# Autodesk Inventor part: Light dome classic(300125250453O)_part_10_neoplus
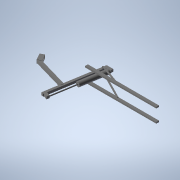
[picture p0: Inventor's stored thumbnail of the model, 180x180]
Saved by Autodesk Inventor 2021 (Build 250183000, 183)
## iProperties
Created: 2026-04
Part Number: Light dome classic(300125250453O)_part_10_neoplus
Material: Generic
Catalog Web Link: www.3dfindit.com
Description: Light dome classic_part_10_neoplus-
Vendor: KINGSPAN
Document SubType Name: Modeling
Designer: psAdmin
Manufacturer: KINGSPAN
Mass: 5382.09 g
Surface Area: 6581.21 cm^2
Volume: 5382.09 cm^3
Density: 1 g/cm^3
Appearance: PSOLRGB-255-255-255
Category: PARTsolutions
Company: KINGSPAN
Title: Light dome classic(300125250453O)_part_10_neoplus
Author: Cadenas PARTsolutions
PSOL_IDENT_0: {$CADENAS_DATA/23d-libs/kingspan_kla/light_dome_classic_neoplus/parts/part_10.prj},291 {VTYP=3D},{NB=
PSOL_IDENT_1: Light dome classic(300125250453O)_part_10_neoplus},{LINA=Light dome classic(300125250453O)_part_10_n
PSOL_IDENT_2: eoplus},{NN=Light dome classic_part_10_neoplus},{DATE=15.07.2024 10:56:16},{GEOMDATE=01.07.2024 07:0
PSOL_IDENT_3: 4:16},{VERSION=},{LINEID=10},{WBVAR=LODLEVEL,L,W,DP,OP,BA,OC},{WBNUMERIC=W}  {NB=Light dome classic(
PSOL_IDENT_4: 300125250453O)_part_10_neoplus},{LINA=Light dome classic(300125250453O)_part_10_neoplus},{KT=DUMMY},
PSOL_IDENT_5: {IDNR=},{PN=Light dome classic},{LODLEVEL=300},{L=125},{W=250},{DRIVE=1},{WX=125,250,300},{DP=4},{OP=
PSOL_IDENT_6: 5},{BA=3},{OC=O},{OPX='5','Pneumatic - NRWG F.6 LK'},{LX=1250},{XWX=2500},{HEI=1214.941},{VER=2},{DP
PSOL_IDENT_7: X='3', 'Fixed','1', 'Natural ventilation' ,'4','NSHE', '2', 'NSHEV'}
NB: Light dome classic(300125250453O)_part_10_neoplus
NN: Light dome classic_part_10_neoplus
NBSYN: $PN.($LODLEVEL.$L.$W.$DP.$OP.$BA.$OC.)_part_10_neoplus
LINA: Light dome classic(300125250453O)_part_10_neoplus
CATALOG: Light + Air
PN: Light dome classic
LODLEVEL: 300
L: 125
W: 250
DP: NSHE
OP: Pneumatic - NRWG F.6 LK
BA: PVC base 50 cm
OC: Open
SUPPLIER: KINGSPAN
ARTICLENO: Light dome classic(300125250453O)_part_10_neoplus
BOMINFO: Light dome classic(300125250453O)_part_10_neoplus
CREATOR: CADENAS GmbH
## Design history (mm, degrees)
sketch "Sketch_2"
  geometry: L1 (-549.928, -221.6)-(-536.377, -261.6); L2 (-536.377, -261.6)-(536.377, -261.6); L3 (536.377, -261.6)-(549.928, -221.6); L4 (549.928, -221.6)-(-549.928, -221.6)
  constraints: 8 end point
extrude "Extrusion1" join sketch "Sketch_2" distance "d0" = 20; taper "d1" = 0 deg
sketch "Sketch_1"
  geometry: L1 (567.69, 169.17)-(525.978, 292.296); L2 (525.978, 292.296)-(519.348, 290.05); L3 (519.348, 290.05)-(561.06, 166.924); L4 (561.06, 166.924)-(567.69, 169.17)
  constraints: 8 end point
extrude "Extrusion2" join sketch "Sketch_1" stored distance "d2" = 220; taper "d3" = 0 deg
sketch "Sketch_3"
  geometry: L1 (-519.348, 290.05)-(-525.978, 292.296); L2 (-525.978, 292.296)-(-567.69, 169.17); L3 (-567.69, 169.17)-(-561.06, 166.924); L4 (-561.06, 166.924)-(-519.348, 290.05)
  constraints: 8 end point
extrude "Extrusion3" join sketch "Sketch_3" stored distance "d4" = 220; taper "d5" = 0 deg
sketch "Sketch_4"
  geometry: L1 (-549.928, -221.6)-(-536.377, -261.6); L2 (-536.377, -261.6)-(536.377, -261.6); L3 (536.377, -261.6)-(549.928, -221.6); L4 (549.928, -221.6)-(-549.928, -221.6)
  constraints: 8 end point
extrude "Extrusion4" join sketch "Sketch_4" distance "d6" = 20; taper "d7" = 0 deg
sketch "Sketch_5"
  geometry: L1 (471.574, 66.971)-(73.269, 244.308); L2 (73.269, 244.308)-(65.134, 226.037); L3 (65.134, 226.037)-(463.44, 48.7); L4 (463.44, 48.7)-(471.574, 66.971)
  constraints: 8 end point
extrude "Extrusion5" join sketch "Sketch_5" stored distance "d8" = 172.9; taper "d9" = 0 deg
sketch "Sketch_8"
  geometry: L1 (5, 420)-(53.95, 27.63); L2 (53.95, 27.63)-(118.95, 27.63); L3 (118.95, 27.63)-(167.9, 420); L4 (167.9, 420)-(167.9, 440); L5 (167.9, 440)-(5, 440); L6 (5, 440)-(5, 420)
  constraints: 12 end point
extrude "Extrusion6" cut sketch "Sketch_8" distance "d10" = 30; taper "d11" = 0 deg
sketch "Sketch_15"
  geometry: L1 (0, 0)-(172.9, 0); L2 (172.9, 0)-(172.9, 419.685); L3 (172.9, 419.685)-(120.498, 5); L4 (120.498, 5)-(52.402, 5); L5 (52.402, 5)-(0, 419.685); L6 (0, 419.685)-(0, 0)
  constraints: 12 end point
extrude "Extrusion7" cut sketch "Sketch_15" distance "d12" = 30; taper "d13" = 0 deg
sketch "Sketch_9"
  geometry: L1 (597.69, 832.67)-(563.148, 838.314); L2 (563.148, 838.314)-(561.535, 828.444); L3 (561.535, 828.444)-(503.858, 848.304); L4 (503.858, 848.304)-(497.505, 808.187); L5 (497.505, 808.187)-(554.991, 788.392); L6 (554.991, 788.392)-(433.471, 44.67); L7 (433.471, 44.67)-(365.9, 44.67); L8 (365.9, 44.67)-(365.9, 4.67); L9 (365.9, 4.67)-(462.4, 4.67); L10 (462.4, 4.67)-(597.69, 832.67)
  constraints: 20 end point
extrude "Extrusion8" join sketch "Sketch_9" stored distance "d14" = 35; taper "d15" = 0 deg
sketch "Sketch_13"
  geometry: L1 (381.219, 36.091)-(507.434, 808.551); L2 (507.434, 808.551)-(515.329, 807.261); L3 (515.329, 807.261)-(455.842, 443.189); L4 (455.842, 443.189)-(481.008, 439.077); L5 (481.008, 439.077)-(417.004, 47.361); L6 (417.004, 47.361)-(391.838, 51.473); L7 (391.838, 51.473)-(389.114, 34.801); L8 (389.114, 34.801)-(381.219, 36.091); L9 (381.219, 36.091)-(507.434, 808.551)
  constraints: 18 end point
revolve "Revolution1" sketch "Sketch_13" stored, may be unused: angle "d16" = 360 deg
sketch "Sketch_10"
  geometry: L1 (1037.283, 453.845)-(547.04, 594.42); L2 (547.04, 594.42)-(536.566, 557.892); L3 (536.566, 557.892)-(1026.809, 417.317); L4 (1026.809, 417.317)-(1037.283, 453.845)
  constraints: 8 end point
extrude "Extrusion9" join sketch "Sketch_10" stored distance "d17" = 42; taper "d18" = 0 deg
sketch "Sketch_11"
  geometry: L1 (1095.857, 359.009)-(1042.285, 455.654); L2 (1042.285, 455.654)-(989.808, 426.565); L3 (989.808, 426.565)-(1043.38, 329.92); L4 (1043.38, 329.92)-(1095.857, 359.009)
  constraints: 8 end point
extrude "Extrusion10" join sketch "Sketch_11" stored distance "d19" = 51.4; taper "d20" = 0 deg
sketch "Sketch_12"
  geometry: L1 (10.7, 100)-(10.7, 3); L2 (10.7, 3)-(40.7, 3); L3 (40.7, 3)-(40.7, 100); L4 (40.7, 100)-(10.7, 100)
  constraints: 8 end point
extrude "Extrusion11" cut sketch "Sketch_12" distance "d21" = 60; taper "d22" = 0 deg
sketch "Sketch_17"
  geometry: L1 (580, 166.924)-(580, 292.296); L2 (580, 292.296)-(525.978, 292.296); L3 (525.978, 292.296)-(519.348, 290.05); L4 (519.348, 290.05)-(522.46, 280.864); L5 (522.46, 280.864)-(522.46, 166.924); L6 (522.46, 166.924)-(580, 166.924)
  constraints: 12 end point
extrude "Extrusion12" cut sketch "Sketch_17" stored distance "d23" = 400; taper "d24" = 0 deg
sketch "Sketch_18"
  geometry: L1 (-519.348, 290.05)-(-525.978, 292.296); L2 (-525.978, 292.296)-(-580, 292.296); L3 (-580, 292.296)-(-580, 166.924); L4 (-580, 166.924)-(-523.95, 166.924); L5 (-523.95, 166.924)-(-523.95, 276.466); L6 (-523.95, 276.466)-(-519.348, 290.05)
  constraints: 12 end point
extrude "Extrusion13" cut sketch "Sketch_18" stored distance "d25" = 400; taper "d26" = 0 deg
node "IP_10_XY"
node "IP_10_YZ"
node "IP_10_ZX"
node "IP_10_X"
node "IP_10_Y"
node "IP_10_Z"
node "IP_10_Center"
body "Solid1"
